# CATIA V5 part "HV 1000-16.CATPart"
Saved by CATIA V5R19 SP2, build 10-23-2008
Part number: HV 1000-16
Bounding box of the stored display mesh (mm): x -24.865 to 24.865, y -24.997 to 24.997, z 0 to 89
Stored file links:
  C:\Users\Bora\Desktop\3D KATI MODEL- CATIA PART\HV serisi\HV 1000\HV 1000-16.CATPart
  C:\Program Files\Dassault Systemes\B19\intel_a\reffiles\standard\MetricThickPitch.txt
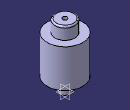
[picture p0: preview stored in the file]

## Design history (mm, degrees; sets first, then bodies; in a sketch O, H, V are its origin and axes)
Body1 (main body)
  Sketch1 on yz-plane, origin (0, 0, 0), H (0, 1, 0), V (0, 0, 1)
    point P1 (14, 87)
    point P3 (14, 87)
    point P8 (8, 17)
    point P10 (8, 1)
    point P11 (8, 17)
    point P12 (8, 1)
    arc A1 centre (12, 87) radius 2 from (14, 87) to (12, 89) ccw
    line L1 (14, 87) -> (14, 72)
    arc A2 centre (8, 18) radius 1 from (8, 19) to (8, 17) ccw
    line L2 (7, 0) -> (8, 1)
    line L3 (8, 17) -> (8, 1)
    line L4 (0, 0) -> (7, 0)
    line L5 (8, 19) -> (25, 19)
    line L6 (14, 72) -> (25, 72)
    line L7 (12, 89) -> (0, 89)
    point P13 (0, 89)
    line L8 (25, 72) -> (25, 19)
    horizontal: L4 H, L5 H, L6 H
    coincidence: P13 V, P1 P3, P8 P11, P10 P12
    tangency: L7 A1
    vertical: L8 V
  Shaft1: profile Sketch1, axis Sketch1.V, angle 360
  Sketch2 on face of Shaft1 from Sketch1.L4, origin (0, 0, 0), H (1, 0, 0), V (0, -1, 0)
    point P1 (0, 0)
  Hole1: placed by Sketch2, at (0, 0, 0) direction (0, 0, 1), diameter 13.835, depth 19, threaded "M16", thread diameter 16, thread depth 19, pitch 2
  Sketch3 on face of Shaft1 from Sketch1.L7, origin (0, 0, 89), H (1, 0, 0), V (0, 1, 0)
    point P1 (0, 0)
  Hole2: placed by Sketch3, at (0, 0, 89) direction (0, 0, -1), diameter 6.647, depth 15, threaded "M8", thread diameter 8, thread depth 15, pitch 1.25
